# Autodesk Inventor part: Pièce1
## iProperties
Author: robert
Shininess: 20.0
Angle Display Precision: 2
Document Length Units: 11269
Document Angle Units: 11283
Document Time Units: 11279
Document Mass Units: 11290
Document Length Units Precision: 3
Document Angle Units Precision: 2
Compacted: True
PropertySet Name: _Private Model Information
Created: 2003-02
Part Number: Pièce1
Material: Par défaut
Document SubType Name: Modélisation
Designer: robert
Control State: 0
Master: False
Checked Out: False
PropertySet Name: Design Tracking Control
Density: 0.0
Volumn: 0.0
Area: 0.0
PropertySet Name: Model Information
